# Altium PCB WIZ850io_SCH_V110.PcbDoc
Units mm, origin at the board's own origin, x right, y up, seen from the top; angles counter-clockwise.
Board outline 23 x 25 mm, 4 copper layers (Top Layer, Internal Plane 1, Internal Plane 2, Bottom Layer); 39 components, 31 nets, 148 pads, 214 vias.
Unrouted connection lines stored in the file: 1.
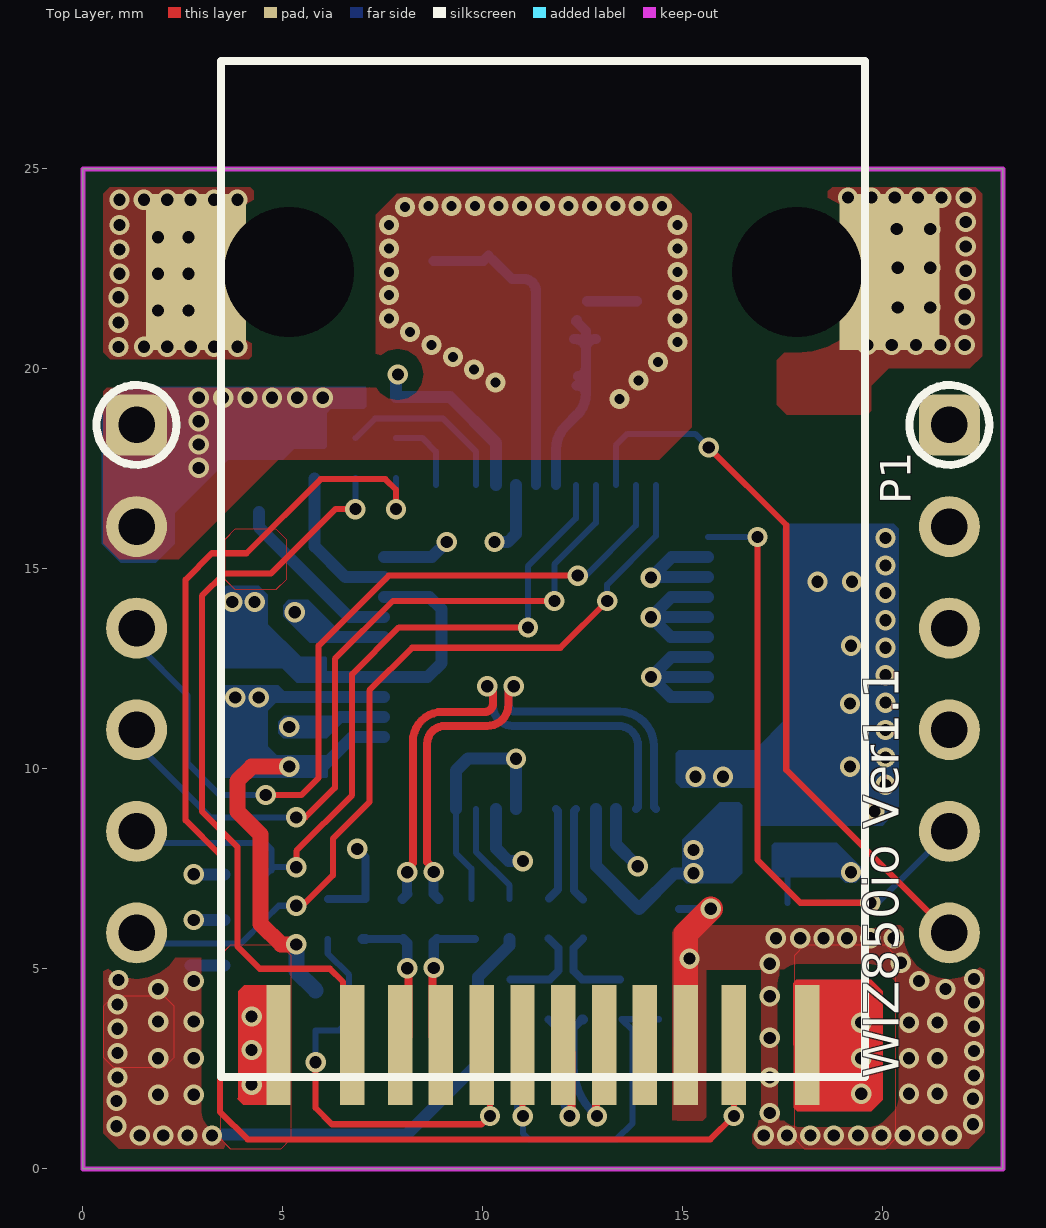
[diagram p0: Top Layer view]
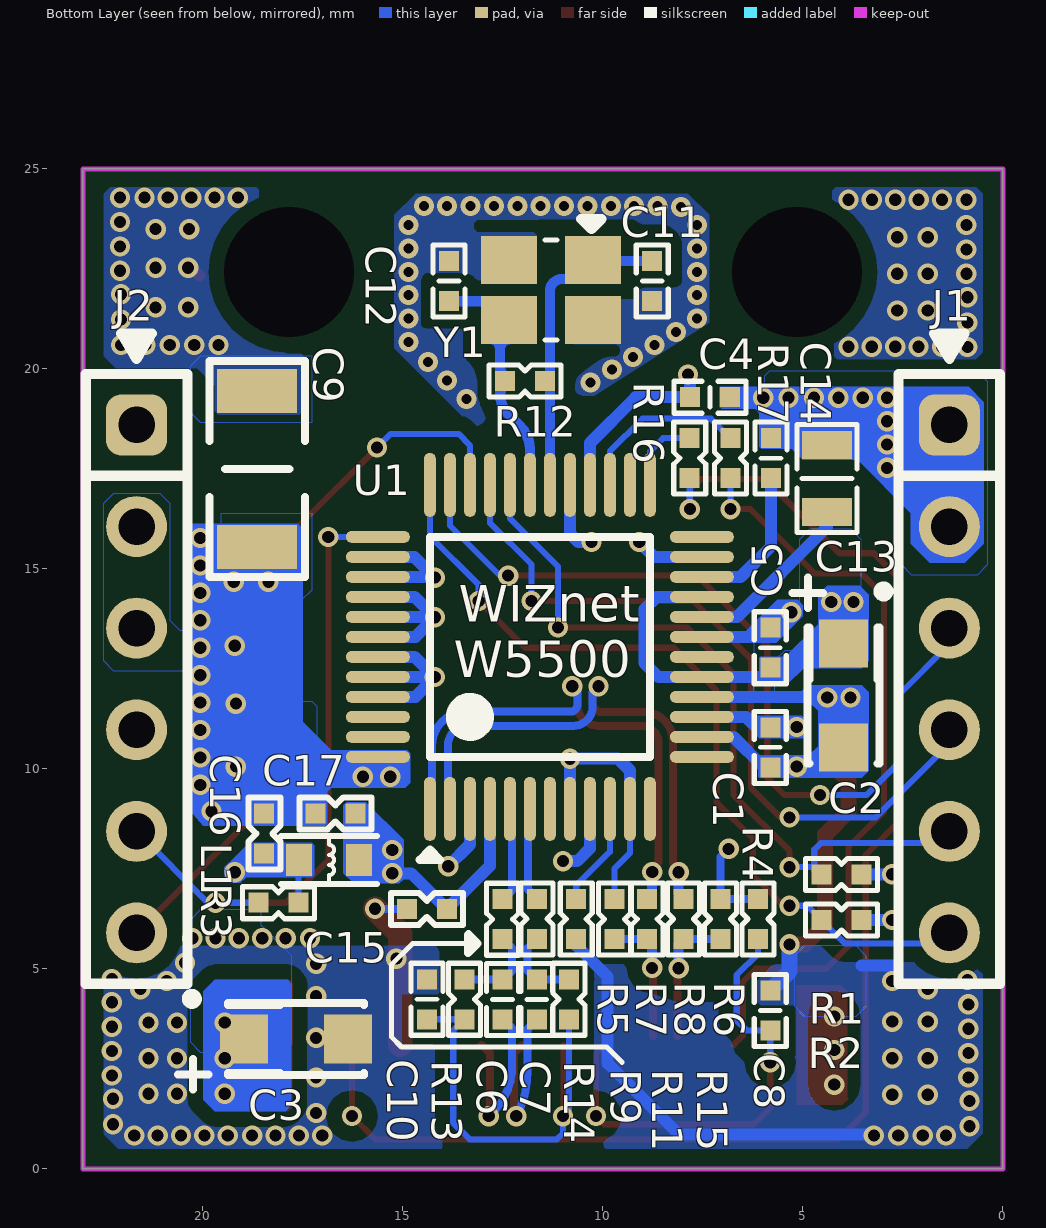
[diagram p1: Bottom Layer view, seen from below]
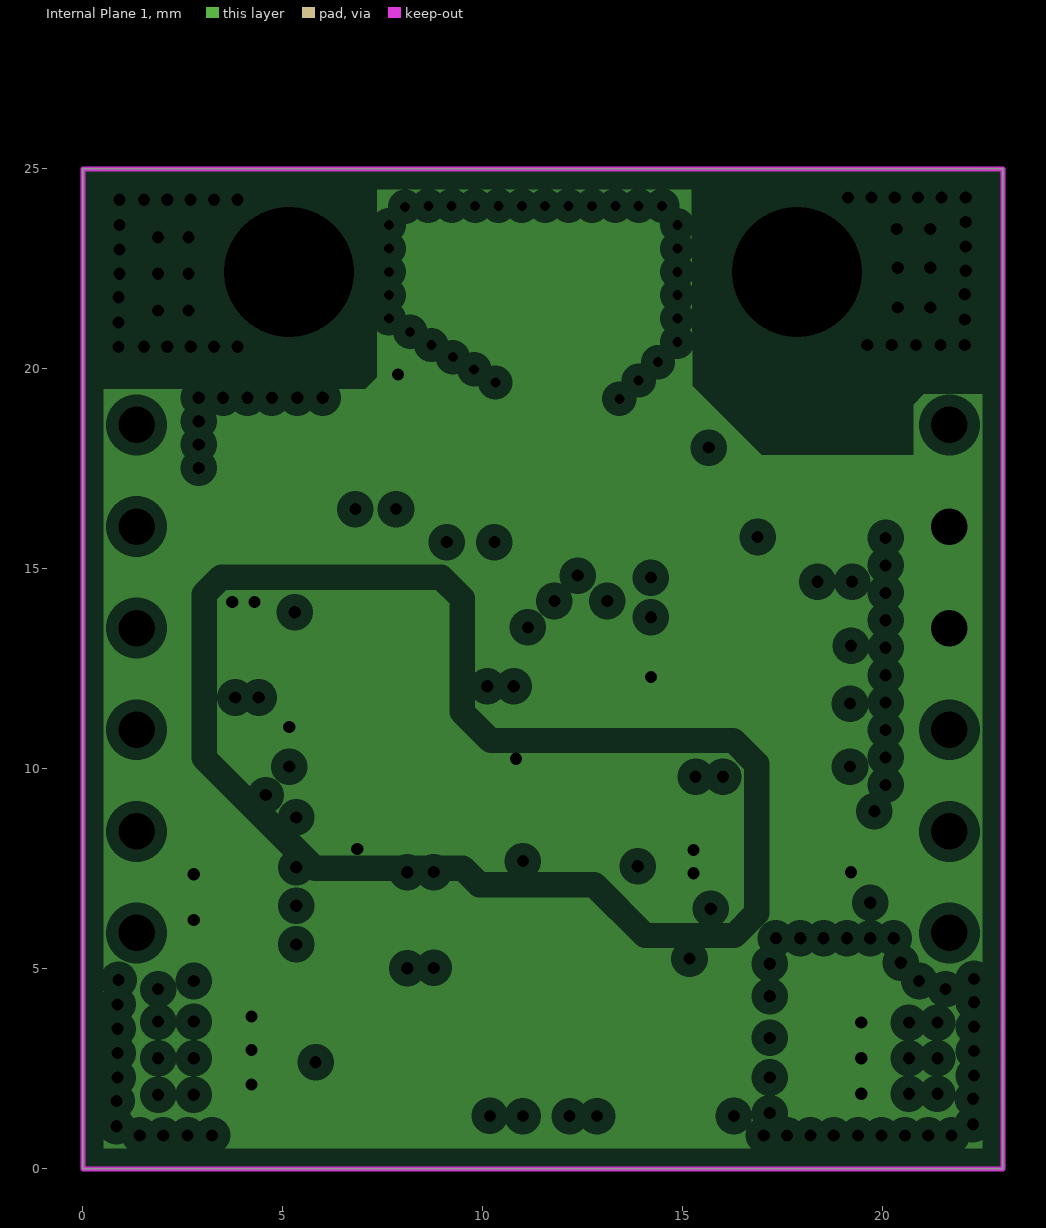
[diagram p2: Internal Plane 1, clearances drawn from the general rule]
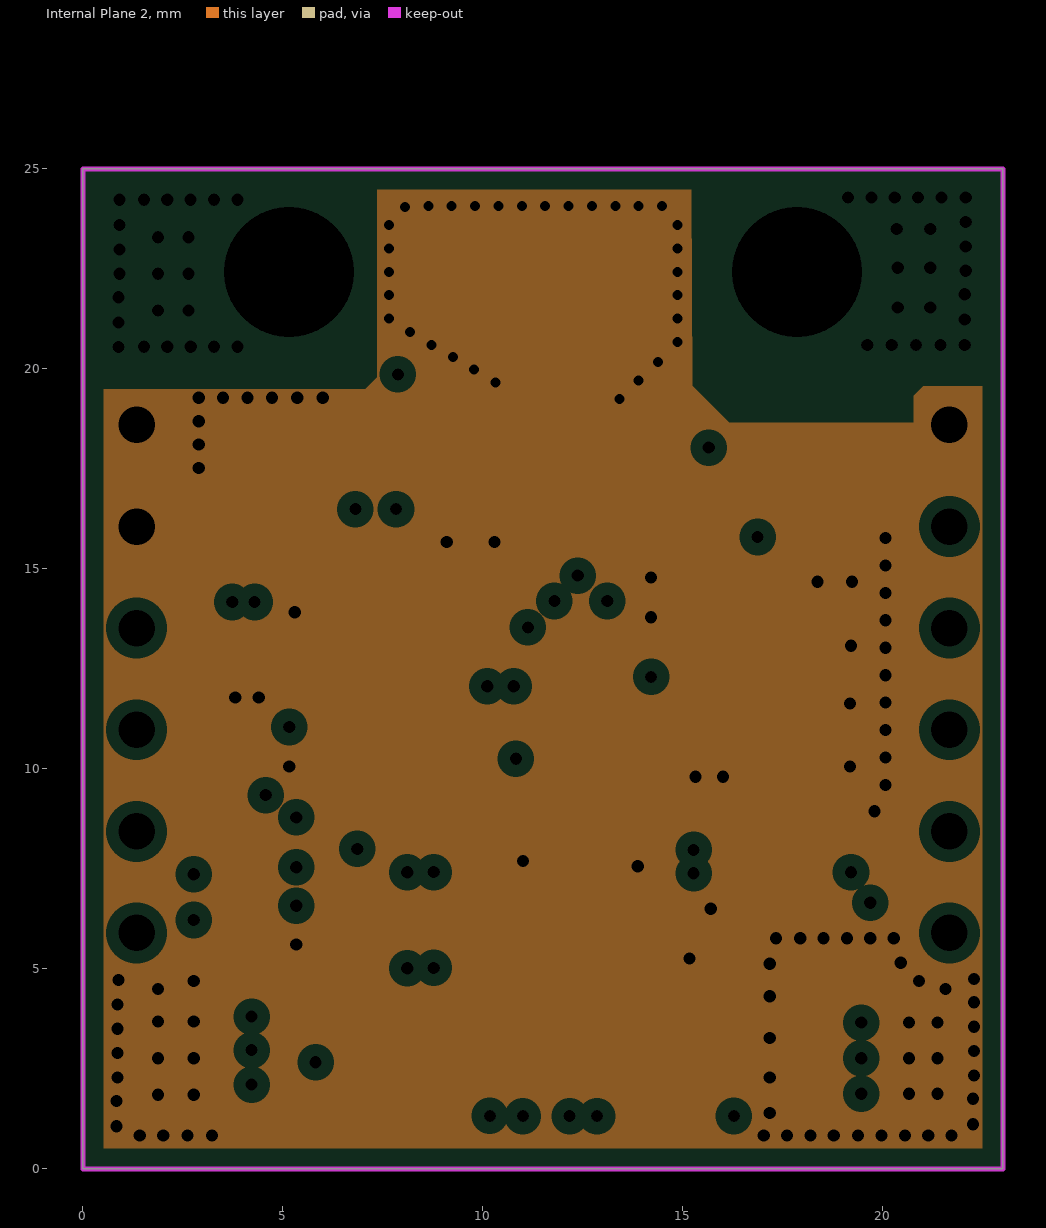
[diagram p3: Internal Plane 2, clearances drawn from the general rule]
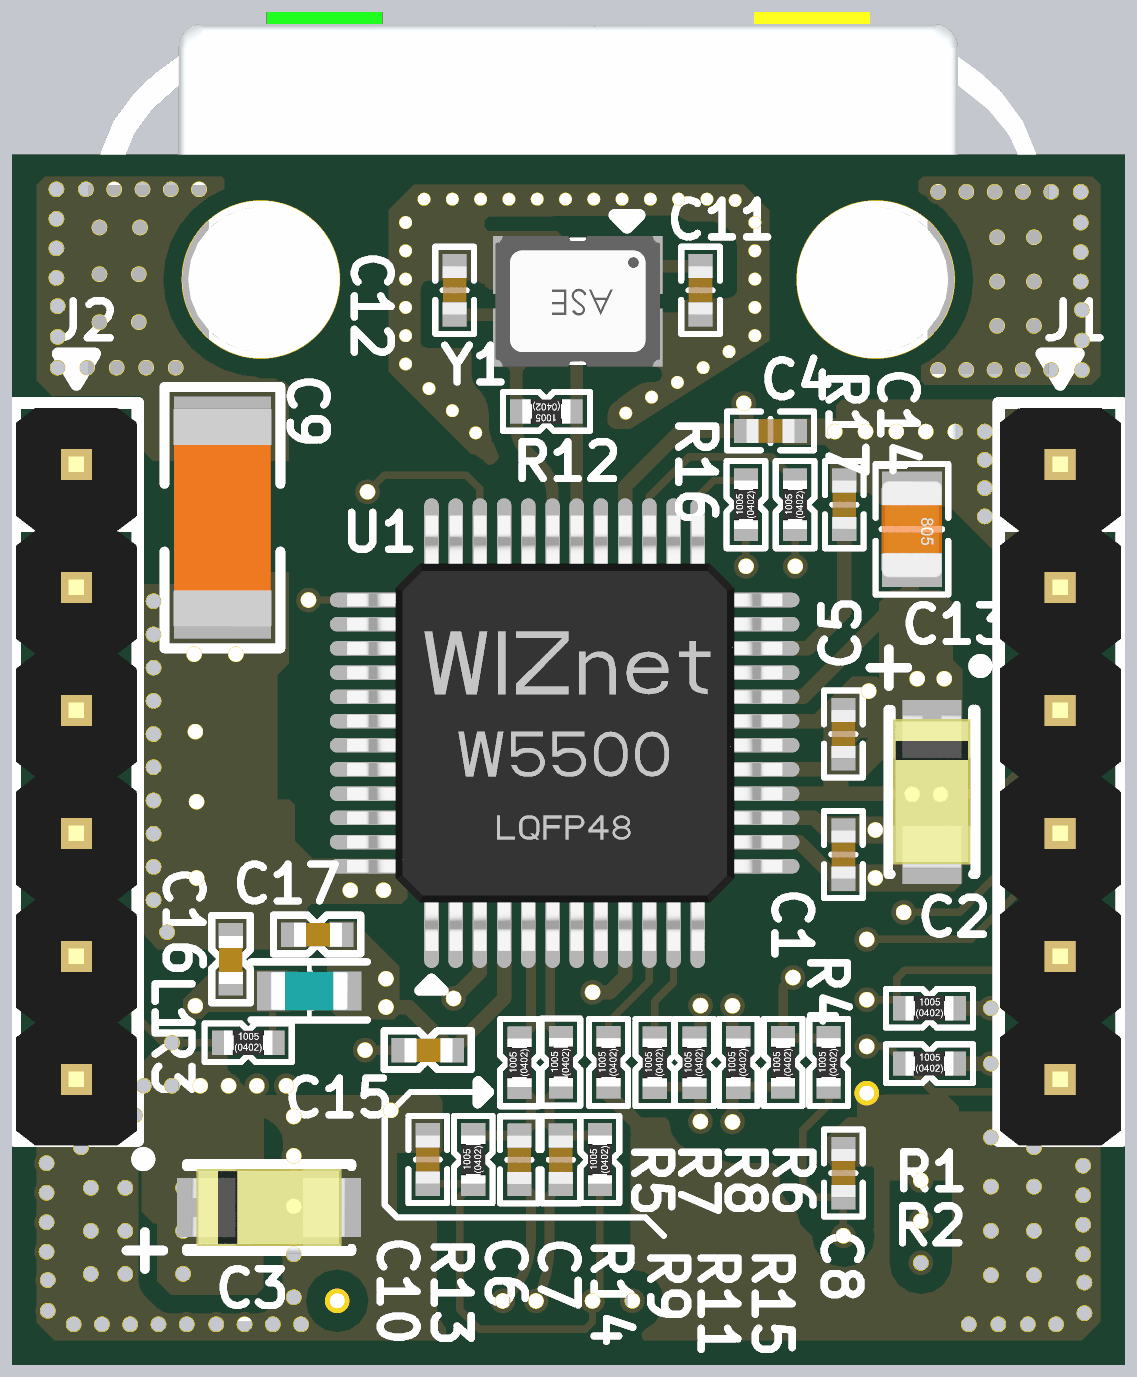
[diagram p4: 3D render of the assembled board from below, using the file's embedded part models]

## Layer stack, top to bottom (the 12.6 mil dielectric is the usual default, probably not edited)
Top Solder: solder mask 0.0102, Solder Resist, Dk 3.5
Top Layer: signal copper 0.0356
Dielectric1: dielectric 0.32, FR-4, Dk 4.8
Internal Plane 1: plane copper 0.0356, net 3.3V_D
Dielectric2: dielectric 0.32, FR-4, Dk 4.8
Internal Plane 2: plane copper 0.0356, net GND
Dielectric3: dielectric 0.32, FR-4, Dk 4.8
Bottom Layer: signal copper 0.0356
Bottom Solder: solder mask 0.0102, Solder Resist, Dk 3.5

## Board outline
0,0 23,0 23,25 0,25

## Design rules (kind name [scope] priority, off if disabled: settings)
Clearance [All] p1: gap=0.152 ignorepadtopadclearanceinfootprint=FALSE except(0: Arc-Hole Track-Hole SMDPad-Hole THPad-Hole Via-Hole Fill-Hole Poly-Hole Region-Hole Text-Hole; 0.381: Arc-Poly Track-Poly SMDPad-Poly THPad-Poly Via-Poly Fill-Poly Poly-Poly Poly-Region)
DiffPairsRouting [All] p1: maxlimit=0.152 minlimit=0.152 mostfreqgap=0.152 toplayer_minwidth=0.152 toplayer_maxwidth=0.152 toplayer_prefwidth=0.152 bottomlayer_minwidth=0.152 bottomlayer_maxwidth=0.152 bottomlayer_prefwidth=0.152 maxuncoupledlength=12.7
HoleSize [All] p1: absolutevalues=TRUE maxlimit=25.4 minlimit=0.025 maxpercent=80.000 minpercent=20.000
PlaneClearance [All] p1: clearance=0.305
PlaneConnect [All] p1: planeconnectstyle=Direct reliefexpansion=0.508 reliefentries=4 reliefconductorwidth=0.254 reliefairgap=0.254
PolygonConnect [All] p1: connectstyle=Direct reliefconductorwidth=0.254 reliefentries=4 polygonreliefangle="90 Angle" airgapwidth=0.254
RoutingVias [All] p1: holewidth=0.305 width=0.508 viastyle="Through Hole" minholewidth=0.305 minwidth=0.508 maxholewidth=0.711 maxwidth=1.27
SolderMaskExpansion [All] p1: expansion=0 istentingtop=FALSE
Width [All] p1: maxlimit=1 minlimit=0.15 preferedwidth=0.15 minimp=50.000000 maximp=50.000000 favimp=50.000000
26 further rules are at their usual default settings.

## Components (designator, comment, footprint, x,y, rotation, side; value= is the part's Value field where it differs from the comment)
C1 "0.1uF" CAP-0402#1 5.817,10.541 r90 bottom
C2 "10uF/16V" "CAP-A SIZE" 3.988,11.836 r270 bottom
C3 "10uF/16V" "CAP-A SIZE" 17.678,3.251 r180 bottom
C4 "0.1uF" CAP-0402#1 7.322,19.293 r0 bottom
C5 "1uF" CAP-0402#1 5.817,13.03 r270 bottom
C6 "6.8nF" CAP-0402#1 12.51,4.237 r90 bottom
C7 "6.8nF" CAP-0402#1 11.654,4.239 r90 bottom
C8 "22nF" CAP-0402#1 5.817,3.962 r270 bottom
C9 "1nF/2kV" CAP-1808 18.644,17.501 r90 bottom
C10 "10nF" CAP-0402#1 14.402,4.242 r270 bottom
C11 "18pF" CAP-0402#1 8.767,22.197 r90 bottom
C12 "18pF" CAP-0402#1 13.847,22.197 r270 bottom
C13 "4.7uF" CAP-0805 4.401,17.261 r270 bottom
C14 "10nF" CAP-0402#1 5.798,17.769 r270 bottom
C15 "0.1uF" CAP-0402#2 14.402,6.502 r180 bottom
C16 "0.1uF" CAP-0402#2 18.466,8.382 r270 bottom
C17 "0.1uF" CAP-0402#2 16.688,8.89 r180 bottom
J1 "2.54mm 1x6 Pin Header DIP" IDC-1X6 1.34,18.6 r270 bottom locked
J2 "2.54mm 1x6 Pin Header DIP" IDC-1X6 21.66,18.6 r270 bottom locked
L1 "HH-1M1608-121JT" IND-0603 16.85,7.725 r180 bottom
P1 "BS-R250210" BS-R250210 11.5,15 r180 top locked
R1 "4.7K" RES-0402 4.039,7.366 r180 bottom
R2 "4.7K" RES-0402 4.039,6.223 r180 bottom
R3 "4.7K" RES-0402 18.11,6.655 r180 bottom
R4 "10R" RES-0402 6.121,6.248 r90 bottom
R5 "49R9" RES-0402 9.713,6.245 r90 bottom
R6 "49R9" RES-0402 7.061,6.248 r90 bottom
R7 "33R" RES-0402 8.893,6.245 r90 bottom
R8 "33R" RES-0402 7.988,6.247 r90 bottom
R9 "33R" RES-0402 12.507,6.243 r90 bottom
R11 "33R" RES-0402 11.651,6.252 r90 bottom
R12 "1M" RES-0402 11.951,19.695 r0 bottom
R13 "49R9" RES-0402 13.462,4.242 r90 bottom
R14 "49R9" RES-0402 10.846,4.242 r90 bottom
R15 "12.4K" RES-0402 10.668,6.248 r90 bottom
R16 "330R" RES-0402 7.83,17.769 r90 bottom
R17 "330R" RES-0402 6.814,17.769 r90 bottom
U1 "W5500" "WIZNET W5500" 11.575,13.05 r180 bottom locked
Y1 "25MHz" OSC-82J0626 11.303,21.971 r0 bottom

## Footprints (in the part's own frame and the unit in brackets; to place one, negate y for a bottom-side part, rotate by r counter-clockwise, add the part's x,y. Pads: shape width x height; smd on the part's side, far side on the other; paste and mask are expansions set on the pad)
BS-R250210 [mm] "BS-R250210"
  rect 0.61x3 smd: L1(6.61,11.9) L2(4.77,11.9) L3(-4.77,11.9) L4(-6.61,11.9) R1(3.57,11.9) R2(2.55,11.9) R3(1.53,11.9) R4(0.51,11.9) R5(-0.51,11.9) R6(-1.53,11.9) R7(-2.55,11.9) R8(-3.57,11.9)
  rect 2.5x3.9 smd: S1(-8.67,-7.42) S2(8.67,-7.42)
  round 0 hole 3.25: ""(-6.35,-7.42) ""(6.35,-7.42)
  silkscreen extent -8.05,-12.7 8.05,12.7, body extent -9.75,-12.95 9.75,14.1, height 14.58
CAP-0402#1 [mm] "Ceramic CAP 0402(1005)"
  rect 0.5x0.5 smd: 1(-0.5,0) 2(0.5,0)
  silkscreen extent -0.9,-0.4 0.9,0.4, body extent -0.5,-0.25 0.5,0.25, height 0.6
CAP-0402#2 [mm] "Ceramic CAP 0402(1005)"
  rect 0.5x0.5 smd: 1(-0.5,-0.004) 2(0.5,-0.004)
  silkscreen extent -0.9,-0.4 0.9,0.4, body extent -0.48,-0.25 0.52,0.25, height 0.6
CAP-0805 [mm] "Ceramic CAP 0805(2012)"
  rect 0.7x1.245 smd: 1(-0.839,0) 2(0.839,0)
  silkscreen extent -1.35,-0.75 1.35,0.75, body extent -1,-0.62 1,0.62, height 0.78
CAP-1808 [mm] "Ceramic CAP 1808(4520)"
  rect 1.1x2 smd: 1(-1.95,0) 2(1.95,0)
  silkscreen extent -2.7,-1.2 2.7,1.2, body extent -2.25,-1.02 2.25,1.01, height 2
"CAP-A SIZE" [mm] "Tantal CAP A Size EIA/IECQ 3216"
  rect 1.2x1.22 smd: 1(-1.3,0) 2(1.3,0)
  silkscreen extent -2.95,-1.27 1.7,1.12, body extent -1.6,-0.8 1.59,0.8
IDC-1X6 [mil]
  rrect50% 60x60 hole 36: 1(0,0)
  round 60 hole 36: 2(100,0) 3(200,0) 4(300,0) 5(400,0) 6(500,0)
  silkscreen extent -90,-50 550,50, body extent -46,-49 554,49, height 323
IND-0603 [mm] "Inductor 0603(1608)"
  rect 0.65x0.8 smd: 1(-0.75,0) 2(0.75,0)
  silkscreen extent -1.2,-0.6 1.2,0.6, body extent -0.8,-0.4 0.8,0.4, height 0.95
OSC-82J0626 [mm]
  rect 1.4x1.2 smd: 1(-1.05,-0.75) 2(1.05,-0.75) 3(1.05,0.75) 4(-1.05,0.75)
  silkscreen extent -1.27,-1.78 0.15,1.25, body extent -1.7,-1.35 1.7,1.35, height 1.06
RES-0402 [mm]
  rect 0.5x0.5 smd: 1(-0.5,0) 2(0.5,0)
  silkscreen extent -0.9,-0.4 0.9,0.4, body extent -0.5,-0.25 0.5,0.25, height 0.35
"WIZNET W5500" [mm]
  oval 0.3x1.6 smd: 1(-2.75,-4.05) 2(-2.25,-4.05) 3(-1.75,-4.05) 4(-1.25,-4.05) 5(-0.75,-4.05) 6(-0.25,-4.05) 7(0.25,-4.05) 8(0.75,-4.05) 9(1.25,-4.05) 10(1.75,-4.05) 11(2.25,-4.05) 12(2.75,-4.05) 25(2.75,4.05) 26(2.25,4.05) 27(1.75,4.05) 28(1.25,4.05) 29(0.75,4.05) 30(0.25,4.05) 31(-0.25,4.05) 32(-0.75,4.05) 33(-1.25,4.05) 34(-1.75,4.05) 35(-2.25,4.05) 36(-2.75,4.05)
  oval 1.6x0.3 smd: 13(4.05,-2.75) 14(4.05,-2.25) 15(4.05,-1.75) 16(4.05,-1.25) 17(4.05,-0.75) 18(4.05,-0.25) 19(4.05,0.25) 20(4.05,0.75) 21(4.05,1.25) 22(4.05,1.75) 23(4.05,2.25) 24(4.05,2.75) 37(-4.05,2.75) 38(-4.05,2.25) 39(-4.05,1.75) 40(-4.05,1.25) 41(-4.05,0.75) 42(-4.05,0.25) 43(-4.05,-0.25) 44(-4.05,-0.75) 45(-4.05,-1.25) 46(-4.05,-1.75) 47(-4.05,-2.25) 48(-4.05,-2.75)
  silkscreen extent -3,-5.32 2.75,2.75, body extent -4.5,-4.5 4.5,4.5, height 1.65

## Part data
C1 C4 C5 C6 C7 C8 C10 C11 C12 C13 C15 C16 C17: library part CAP-0402, "Ceramic CAP 0402(1005)"
C2 C3: library part "CAP-A Size", "Tantla CAP A Size EIA/IECQ 3216"
C9: library part CAP-1808, "Ceramic CAP 1808(4520)"
C14: library part CAP-0805, "Ceramic CAP 0805(2012)"
L1: library part IND-0603, "Inductor 0603(1608)"
R1 R2 R3 R4 R5 R6 R7 R8 R9 R11 R12 R13 R14 R15 R16 R17: library part RES-0402, "RES-0402"
U1: "WIZnet W5500"
Y1: library part OSC-82J0626-25MHz, "X-tal 25MHz,3.2x2.5 SMD, CL=18pF"

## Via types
v1: diameter 0.508, hole 0.305, Top Layer to Bottom Layer, tented both sides, 181 vias
v2: diameter 0.5, hole 0.25, Top Layer to Bottom Layer, tented both sides, 31 vias
v3: diameter 0.508, hole 0.305, Top Layer to Bottom Layer, 2 vias

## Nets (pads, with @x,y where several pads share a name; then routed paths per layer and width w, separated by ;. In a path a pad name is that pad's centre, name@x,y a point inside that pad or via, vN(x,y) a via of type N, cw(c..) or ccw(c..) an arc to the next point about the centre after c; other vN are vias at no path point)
3.3V_A: C1.2 C2.1 C5.2 C15.2 C17.2 L1.2 R4.2 R5.2 R6.2 U1.4 U1.8 U1.11 U1.15 U1.17 U1.21 | length 21.8
  Bottom Layer w0.152: U1.11 9.325,7.896 9.713,7.508 R5.2
  Bottom Layer w0.2: R4.2 R6.2 7.061,7.798 v1(6.858,8.001)
  Bottom Layer w0.3: v1(5.156,11.049) 5.164,11.041 C1.2@5.842,11.041 ; C5.2@5.817,12.403 5.92,12.3 U1.17 7.531,12.294 8.611,12.294 8.966,12.649 8.966,13.995 8.662,14.3 U1.21 ; C1.2@6.045,10.947 6.071,10.947 6.423,11.3 U1.15 ; U1.11 9.325,9.96 9.627,10.262 10.82,10.262 v1(10.825,10.257) U1.8 ; U1.4 12.825,7.575 C15.2 14.795,7.391 v1(15.265,7.391)
  other v1: 15.265,7.976 3.734,14.173 4.293,14.173
3.3V_D: C3.1 C4.2 C16.2 J2.2 J2.3 L1.1 P1.L1 P1.L4 R1.2 R2.2 R3.2 U1.28 U1.43 U1.44 U1.45 | length 11.9
  Bottom Layer w0.152: R3.2 L1.1@17.61,7.715
  Bottom Layer w0.3: v1(2.769,6.223) R2.2 ; v1(2.769,7.366) R1.2 ; v1(7.874,19.863) 7.822,19.811 C4.2 9.181,19.293 10.325,18.148 U1.28 ; U1.45 14.692,11.8 14.205,12.287 v1(14.205,12.3) ; U1.44 v1(14.205,12.3) ; U1.43 14.705,12.8 v1(14.205,12.3) ; L1.1 L1.1@17.603,7.722 ; L1.1@17.61,7.715 L1.1@17.603,7.722 ; L1.1@17.629,7.696 L1.1@17.603,7.722
  other v1: 19.456,1.88 4.216,2.108 19.456,2.769 4.216,2.972 19.456,3.658 4.216,3.81 19.202,7.417
ACT_LED: R17.2 U1.27 | length 4.4
  Bottom Layer w0.152: R17.2 7.302,18.757 9.005,18.757 9.825,17.937 U1.27
CH_GND: C9.2 P1.S1 P1.S2 | length 0.1
  Top Layer w0.3: P1.S1@20.091,22.341 P1.S1
  other v1: 0.889,20.549 1.525,20.552 2.109,20.552 2.693,20.552 3.278,20.552 3.862,20.552 19.609,20.599 20.218,20.599 20.828,20.599 21.438,20.599 22.047,20.599 0.889,21.158 22.047,21.234 1.88,21.463 2.642,21.463 20.371,21.539 21.184,21.539 0.889,21.793 22.047,21.869 0.914,22.377 1.88,22.377 2.642,22.377 22.073,22.454 20.371,22.53 21.184,22.53 0.914,22.987 22.073,23.063 1.88,23.292 2.642,23.292 20.345,23.495 21.184,23.495 0.914,23.597 22.073,23.673 0.914,24.232 1.524,24.232 2.108,24.232 2.692,24.232 3.277,24.232 3.861,24.232 19.126,24.282 19.71,24.282 20.295,24.282 20.879,24.282 21.463,24.282 22.073,24.282
GND: C1.1 C2.2 C3.2 C4.1 C5.1 C8.1 C9.1 C10.1 C11.1 C12.1 C13.1 C14.1 C15.1 C16.1 C17.1 J1.1 J1.2 J2.1 P1.R8 R15.1 U1.3 U1.9 U1.14 U1.16 U1.19 U1.23 U1.29 U1.38 U1.39 U1.40 U1.41 U1.42 U1.48 Y1.2 Y1.4 | length 47.2
  Top Layer w0.4: v1(5.156,10.058) 4.216,10.058 3.861,9.703 3.861,8.941 4.445,8.357 4.445,6.121 4.953,5.613 v3(5.334,5.613)
  Top Layer w0.61: P1.R8 15.07,5.875 v1(15.697,6.502)
  Bottom Layer w0.2: C15.1 14.906,6.502 v1(15.697,6.502)
  Bottom Layer w0.3: 2.692,5.08 3.539,5.08 ; v1(3.226,0.838) 3.251,0.864 8.103,0.864 9.881,2.642 9.881,4.801 10.668,5.588 R15.1 ; v1(4.394,11.786) 4.347,11.786 4.332,11.8 U1.16 ; v1(5.156,10.058) 5.994,10.058 6.735,10.8 U1.14 ; C5.1@5.817,13.403 5.92,13.3 U1.19 ; U1.23 8.721,15.3 v1(9.093,15.672) ; v1(10.287,15.672) 10.617,15.672 10.825,15.88 U1.29 ; U1.9 10.325,8.014 10.643,7.696 v1(10.998,7.696) ; U1.3 13.325,8.113 v1(13.868,7.569) ; v1(14.199,14.783) v1@14.216,14.8 ; U1.42 14.691,13.3 v1(14.199,13.792) v1@14.206,13.8 ; U1.41 v1@14.206,13.8 ; U1.40 14.706,14.3 v1@14.206,13.8 ; U1.39 v1@14.216,14.8 ; U1.38 14.716,15.3 v1@14.216,14.8 ; v1@19.346,10.1 19.844,9.601 v1(20.066,9.601)
  Bottom Layer w0.4: v3(5.334,5.613) 5.334,4.945 C8.1
  other v1: 1.422,0.838 2.007,0.838 2.616,0.838 17.018,0.838 17.602,0.838 18.186,0.838 18.771,0.838 19.38,0.838 19.964,0.838 20.549,0.838 21.133,0.838 21.717,0.838 0.838,1.067 22.25,1.118 17.17,1.397 0.838,1.702 22.25,1.753 1.88,1.854 2.769,1.854 20.65,1.88 21.361,1.88 0.864,2.286 17.17,2.286 22.276,2.337 1.88,2.769 2.769,2.769 20.65,2.769 21.361,2.769 0.864,2.896 22.276,2.946 17.17,3.277 0.864,3.505 22.276,3.556 20.65,3.658 21.361,3.658 1.88,3.683 2.769,3.683 0.864,4.115 22.276,4.166 17.17,4.318 1.88,4.496 21.565,4.496 2.769,4.699 20.904,4.699 0.889,4.724 22.276,4.75 17.17,5.131 20.447,5.156 15.164,5.258 17.323,5.766 17.932,5.766 18.517,5.766 19.101,5.766 19.685,5.766 20.269,5.766 19.787,8.941 15.316,9.804 16.002,9.804 19.177,10.058 20.066,10.287 20.066,10.973 19.177,11.633 20.066,11.659 3.81,11.786 20.066,12.344 20.066,13.03 19.202,13.081 20.066,13.716 5.294,13.918 20.066,14.402 18.364,14.681 19.228,14.681 20.066,15.088 20.066,15.773 2.896,17.526 2.896,18.11 2.896,18.694 2.896,19.279 3.505,19.279 4.115,19.279 4.724,19.279 5.359,19.279 5.994,19.279
  other v2: 13.411,19.253 10.312,19.66 13.894,19.71 9.779,19.99 14.376,20.168 9.246,20.295 8.712,20.599 14.859,20.676 8.179,20.93 7.645,21.26 14.859,21.26 7.645,21.844 14.859,21.844 7.645,22.428 14.859,22.428 7.645,23.012 14.859,23.012 7.645,23.597 14.859,23.597 8.052,24.054 8.636,24.079 9.22,24.079 9.804,24.079 10.389,24.079 10.973,24.079 11.557,24.079 12.141,24.079 12.725,24.079 13.31,24.079 13.894,24.079 14.478,24.079
INTN: J1.6 R2.1 U1.36 | length 21
  Top Layer w0.152: v1(5.334,6.579) 5.486,6.579 6.248,7.341 6.248,8.255 7.163,9.169 7.163,11.963 8.23,13.03 11.938,13.03 v1(13.106,14.199)
  Bottom Layer w0.152: J1.6 1.601,5.639 3.954,5.639 R2.1 4.894,6.579 v1(5.334,6.579) ; v1(13.106,14.199) 13.106,14.605 14.325,15.824 U1.36
LINK_LED: R16.2 U1.25 | length 2
  Bottom Layer w0.152: R16.2 8.492,18.269 8.825,17.935 U1.25
MISO: J2.6 U1.34 | length 18.2
  Top Layer w0.152: v1(15.646,18.034) 17.582,16.098 17.582,9.978 J2.6
  Bottom Layer w0.152: U1.34 13.325,18.09 13.61,18.375 15.305,18.375 v1(15.646,18.034)
MOSI: J1.3 U1.35 | length 21.2
  Top Layer w0.152: v1(4.572,9.347) 5.461,9.347 5.893,9.779 5.893,13.081 7.645,14.834 v1(12.37,14.834)
  Bottom Layer w0.152: J1.3 1.34,13.113 2.616,11.836 2.616,10.146 3.415,9.347 v1(4.572,9.347) ; v1(12.37,14.834) 12.573,14.834 13.825,16.086 U1.35
NetC6_1: C6.1 P1.R6 | length 4.6
  Top Layer w0.2: v1(12.852,1.321) 12.824,1.349 12.824,2.894 P1.R6
  Bottom Layer w0.2: C6.1@12.48,3.739 12.268,3.527 12.268,2.591 ccw(c13.906,2.575) v1(12.852,1.321)
  Bottom Layer w0.256: C6.1@12.48,3.739 C6.1@12.501,3.739
NetC6_2: C6.2 R9.1 R13.2 | length 2.1
  Bottom Layer w0.2: C6.2@12.473,4.741 12.268,4.946 12.268,5.523 R9.1@12.506,5.761 ; C6.2@12.501,4.739 13.421,4.739 R13.2@13.423,4.741
NetC7_1: C7.1 P1.R5 | length 4.4
  Top Layer w0.2: P1.R5 12.217,2.893 v1@12.217,1.372
  Bottom Layer w0.2: C7.1@11.644,3.739 11.887,3.496 11.887,2.429 ccw(c14.159,2.413) v1(12.167,1.321)
NetC7_2: C7.2 R11.1 R14.2 | length 2.2
  Bottom Layer w0.2: R14.2@10.693,4.742 10.696,4.739 C7.2@11.644,4.739 ; R11.1@11.645,5.761 11.887,5.519 11.887,4.955 C7.2@11.673,4.741
NetC8_2: C8.2 P1.R3 R4.1 | length 11.6
  Top Layer w0.152: v1(5.817,2.667) 5.817,1.524 6.223,1.118 9.968,1.118 v1(10.175,1.325) 10.175,2.895 P1.R3
  Bottom Layer w0.152: v1(5.817,2.667) C8.2 6.409,3.462 6.655,3.708 6.655,4.851 6.121,5.385 R4.1 R4.1@6.111,5.738
NetC10_2: C10.2 P1.R4 R13.1 R14.1 | length 11.5
  Top Layer w0.152: v1@10.99,1.177 10.998,1.185 v1(10.998,1.321) 10.99,1.329 P1.R4
  Bottom Layer w0.152: R14.1@10.839,3.746 R14.1@10.843,3.742 ; R14.1@10.852,3.742 10.852,1.467 v1(10.998,1.321) 10.998,0.889 11.151,0.737 13.335,0.737 13.741,1.143 13.741,3.462 R13.1 C10.2
NetC13_2: C13.2 U1.20 | length 4.4
  Bottom Layer w0.3: C13.2 4.401,16.046 6.647,13.8 U1.20
NetC14_2: C14.2 U1.22 | length 3.8
  Bottom Layer w0.152: C14.2@5.795,17.265 C14.2
  Bottom Layer w0.3: C14.2@5.795,17.265 5.795,15.567 6.561,14.8 U1.22
NetP1_L2: P1.L2 R17.1 | length 19.3
  Top Layer w0.152: P1.L2 6.502,3.328 6.502,4.674 6.172,5.004 4.42,5.004 3.861,5.563 3.861,8.052 2.972,8.941 2.972,14.326 3.531,14.884 4.699,14.884 6.311,16.496 v1(6.811,16.496)
  Bottom Layer w0.152: v1(6.811,16.496) 6.814,16.499 R17.1
NetP1_L3: P1.L3 R16.1 | length 36.5
  Top Layer w0.152: v1(7.827,16.496) 7.827,16.979 7.559,17.247 5.944,17.247 4.089,15.392 3.226,15.392 2.565,14.732 2.565,8.712 3.429,7.849 3.429,1.422 4.115,0.737 15.687,0.737 v3(16.273,1.323) 16.273,3.097 P1.L3
  Bottom Layer w0.152: v1(7.827,16.496) 7.83,16.499 R16.1
NetP1_R1: P1.R1 R6.1 R8.1 | length 3.5
  Top Layer w0.2: v1(8.108,5.017) 8.135,4.99 P1.R1@8.135,3.305
  Bottom Layer w0.2: R6.1@7.061,5.745 7.063,5.747 R8.1
  Bottom Layer w0.254: R6.1@6.996,5.745 R6.1@7.061,5.745 ; R8.1@8.01,5.742 8.108,5.644 v1(8.108,5.017)
NetP1_R2: P1.R2 R5.1 R7.1 | length 3.4
  Top Layer w0.2: P1.R2@8.745,3.305 8.745,5.002 v1(8.77,5.027)
  Bottom Layer w0.2: R7.1@8.852,5.748 R5.1@9.804,5.748
  Bottom Layer w0.254: v1(8.77,5.027) 8.77,5.666 R7.1@8.852,5.748
NetR7_2: R7.2 U1.1 | length 13.4
  Top Layer w0.2: v1@8.768,7.508 8.606,7.67 8.606,10.636 cw(c9.044,10.636) 9.044,11.074 10.107,11.074 ccw(c10.107,11.606) 10.638,11.606 10.638,11.934 v1(10.77,12.065)
  Top Layer w0.25: v1(8.768,7.422) v1@8.768,7.508
  Bottom Layer w0.2: v1(10.77,12.065) 10.639,11.934 10.639,11.609 ccw(c10.816,11.609) 10.816,11.431 13.417,11.431 cw(c13.417,10.576) 14.272,10.576 14.272,9.053 U1.1
  Bottom Layer w0.25: v1(8.768,7.422) 8.768,6.87 R7.2
NetR8_2: R8.2 U1.2 | length 13.4
  Top Layer w0.2: v1@8.107,7.512 8.248,7.653 8.248,10.686 cw(c8.988,10.686) 8.988,11.427 10.044,11.427 ccw(c10.044,11.638) 10.255,11.638 10.255,11.919 v1(10.109,12.065)
  Top Layer w0.25: v1(8.107,7.418) v1@8.107,7.512
  Bottom Layer w0.2: v1(10.109,12.065) 10.257,11.917 10.257,11.564 ccw(c10.742,11.564) 10.742,11.079 13.377,11.079 cw(c13.377,10.578) 13.878,10.578 13.878,9.053 U1.2
  Bottom Layer w0.25: R8.2 8.115,6.874 8.107,6.882 v1(8.107,7.418)
NetR9_2: R9.2 U1.5 | length 2.4
  Bottom Layer w0.2: U1.5 12.271,8.946 12.271,6.964 R9.2@12.5,6.735
NetR11_2: R11.2 U1.6 | length 2.3
  Bottom Layer w0.2: R11.2@11.651,6.764 11.875,6.988 11.875,8.95 U1.6
NetR15_2: R15.2 U1.10 | length 2.6
  Bottom Layer w0.152: U1.10 9.825,7.93 10.668,7.087 R15.2
RSTN: J2.5 R3.1 U1.37 | length 16.4
  Top Layer w0.152: v1(16.866,15.799) 16.866,7.722 17.932,6.655 v1(19.685,6.655)
  Bottom Layer w0.152: U1.37 v1(16.866,15.799) v1(16.866,15.799) ; R3.1 v1(19.685,6.655) 19.875,6.655 J2.5
SCLK: J1.4 U1.33 | length 19
  Top Layer w0.152: v1(5.334,8.788) 5.563,8.788 6.299,9.525 6.299,12.751 7.747,14.199 v1(11.786,14.199)
  Bottom Layer w0.152: J1.4 1.34,10.632 3.184,8.788 v1(5.334,8.788) ; v1(11.786,14.199) 11.786,15.113 12.825,16.152 U1.33
SCSN: J1.5 R1.1 U1.32 | length 19.3
  Top Layer w0.152: v1(5.334,7.544) 5.334,7.95 6.731,9.347 6.731,12.37 7.899,13.538 v1(11.125,13.538)
  Bottom Layer w0.152: J1.5 1.627,8.153 4.547,8.153 4.716,7.984 R1.1@4.716,7.468 ; R1.1 4.564,7.341 4.767,7.544 v1(5.334,7.544) ; v1(11.125,13.538) 11.125,15.062 12.325,16.262 U1.32
XI: C11.2 R12.1 U1.30 Y1.1 | length 7.7
  Bottom Layer w0.254: C11.2 10.007,22.697 Y1.1@10.142,22.832 ; Y1.1 10.726,22.248 11.021,22.248 cw(c11.021,21.944) 11.325,21.944 U1.30
XO: C12.2 R12.2 U1.31 Y1.3 | length 7.2
  Bottom Layer w0.254: U1.31 11.825,17.988 cw(c12.644,17.988) 12.065,18.567 12.361,18.863 ccw(c11.844,19.38) 12.575,19.38 12.575,20.945 12.326,21.194 Y1.3@12.351,21.219 ; Y1.3@12.273,20.747 cw(c12.309,20.482) 12.575,20.518 cw(c12.814,20.508) Y1.3@12.824,20.748 ; R12.2@12.344,19.583 cw(c12.357,19.367) 12.573,19.38 ; R12.2@12.377,19.819 ccw(c12.364,20.03) 12.575,20.044 ; Y1.3@12.606,21.693 C12.2@13.846,21.693
pads on no net: J2.4 P1. P1.R7 U1.7 U1.12 U1.13 U1.18 U1.24 U1.26 U1.46 U1.47

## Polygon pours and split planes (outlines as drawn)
GND on Top Layer "Top Layer-gnd" (solid, remove dead copper, pour order 66): 0.508,3.302 0.508,5.105 0.686,5.283 13.825,5.283 14.663,6.121 22.162,6.121 22.606,5.664 22.606,0.965 22.149,0.508 0.889,0.508 0.508,0.889
GND on Top Layer "Top Layer-NET" (solid, remove dead copper, shelved, pour order 54): 0.762,4.318 0.508,4.064 0.508,2.794 0.762,2.54 2.032,2.54 2.286,2.794 2.286,4.064 2.032,4.318
3.3V_A on Top Layer "Top Layer-net" (solid, remove dead copper, shelved, pour order 42): 5.08,15.621 5.08,14.732 4.826,14.478 3.81,14.478 3.556,14.732 3.556,15.748 3.81,16.002 4.826,16.002 5.08,15.748
3.3V_D on Top Layer "Keep-Out Layer-No Net" (solid, remove dead copper, shelved, pour order 26): 18.034,5.588 17.78,5.334 17.78,0.762 18.034,0.508 20.066,0.508 20.32,0.762 20.32,5.334 20.066,5.588
3.3V_D on Top Layer "Keep-Out Layer-No Net" (solid, remove dead copper, shelved, pour order 22): 3.683,5.588 3.429,5.334 3.429,0.762 3.683,0.508 4.953,0.508 5.207,0.762 5.207,5.334 4.953,5.588
GND on Top Layer "TOP Layer-gnd" (solid, pour order 76): 0.508,19.533 0.508,15.646 0.908,15.247 2.394,15.247 4.877,17.729 14.405,17.729 15.215,18.539 15.214,23.876 14.707,24.384 7.874,24.384 7.849,24.384 7.341,23.876 7.315,23.851 7.315,21.133 7.315,19.685 7.163,19.533
CH_GND on Top Layer "TOP Layer-CHGND" (solid, remove dead copper, pour order 78): 19.711,18.949 19.621,18.858 17.591,18.859 16.281,20.168 16.281,24.409 16.51,24.638 6.553,24.638 6.553,20.726 6.071,20.244 0.686,20.244 0.508,20.422 0.508,21.463 0.508,24.384 0.762,24.638 22.225,24.638 22.479,24.384 22.479,23.876 22.479,20.32 22.174,20.015 20.142,20.015 19.71,19.583
3.3V_A on Bottom Layer "Top Layer-net" (solid, remove dead copper, shelved, pour order 44): 3.556,15.621 3.556,13.081 3.683,12.954 5.461,12.954 5.715,12.7 5.715,11.684 6.223,11.684 6.223,13.589 5.715,13.589 5.334,13.589 5.08,13.843 5.08,13.97 5.08,15.748 4.826,16.002 3.81,16.002 3.556,15.748
no net on Bottom Layer "Top Layer-net" (solid, remove dead copper, shelved, pour order 40): 20.066,18.669 17.272,18.669 17.272,20.32 20.066,20.32 20.32,20.066 20.32,18.923
3.3V_D on Bottom Layer "Top Layer-net" (solid, remove dead copper, shelved, pour order 38): 18.796,12.446 22.225,12.446 22.479,12.7 22.479,16.637 22.225,16.891 21.082,16.891 20.828,16.637 20.828,16.256 20.828,13.716 20.574,13.462 20.32,13.462 19.05,13.462 18.796,13.208
no net on Bottom Layer "Top Layer-net" (solid, remove dead copper, shelved, pour order 36): 18.415,14.224 17.526,14.224 17.272,14.478 17.272,16.383 19.558,16.383 19.558,14.478 19.304,14.224
3.3V_A on Bottom Layer "Top Layer-NET" (solid, remove dead copper, shelved, pour order 34): 19.685,11.049 19.685,9.652 19.558,9.525 18.796,9.525 18.669,9.652 18.669,11.557 18.796,11.684 19.558,11.684 19.685,11.557
no net on Bottom Layer "Top Layer-NET" (solid, remove dead copper, shelved, pour order 32): 18.161,11.049 18.161,9.652 18.034,9.525 17.272,9.525 17.145,9.652 17.145,11.557 17.272,11.684 18.034,11.684 18.161,11.557
3.3V_D on Bottom Layer "Top Layer-NET" (solid, remove dead copper, shelved, pour order 24): 3.683,5.588 3.429,5.334 3.429,4.064 3.683,3.81 4.953,3.81 5.207,4.064 5.207,5.334 4.953,5.588
3.3V_D on Bottom Layer "Top Layer-net" (solid, remove dead copper, shelved, pour order 56): 20.32,5.334 20.32,3.175 20.066,2.921 18.034,2.921 17.78,3.175 17.78,5.334 18.542,6.096 18.542,6.477 19.304,6.477 20.066,6.477 20.32,6.223
GND on Bottom Layer "Top Layer-gnd" (solid, remove dead copper, shelved, pour order 58): 2.54,17.907 2.54,15.113 2.286,14.859 0.635,14.859 0.381,15.113 0.381,19.685 0.635,19.939 5.842,19.939 5.969,19.812 5.969,18.669 2.794,18.669 2.54,18.415
GND on Bottom Layer "Bottom Xtal-gnd" (solid, remove dead copper, pour order 60): 7.341,21.869 7.341,21.156 11.074,18.788 11.074,18.072 12.764,18.072 15.215,20.523 15.215,23.851 14.681,24.384 7.874,24.384 7.341,23.851
GND on Bottom Layer "Bottom Layer-below gnd" (solid, remove dead copper, pour order 62): 0.508,3.302 0.508,5.575 22.479,5.575 22.479,0.864 22.123,0.508 0.889,0.508 0.508,0.889
CH_GND on Bottom Layer "Bottom Layer-CHGND" (solid, remove dead copper, pour order 72): 19.711,18.949 19.621,18.858 17.591,18.859 16.281,20.168 16.281,24.409 16.51,24.638 6.553,24.638 6.553,20.726 6.071,20.244 0.686,20.244 0.508,20.422 0.508,21.463 0.508,24.384 0.762,24.638 22.225,24.638 22.479,24.384 22.479,23.876 22.479,20.32 22.174,20.015 20.142,20.015 19.71,19.583
GND on Internal Plane 2 (split plane): 15.24,19.583 16.154,18.669 20.752,18.669 20.752,19.329 21.006,19.584 22.49,19.584 22.49,0.51 0.51,0.51 0.51,19.507 7.061,19.507 7.341,19.787 7.341,24.49 15.215,24.49
3.3V_D on Internal Plane 1 (split plane): 15.24,19.583 16.973,17.85 20.752,17.85 20.752,19.102 21.025,19.375 22.49,19.375 22.49,0.51 0.51,0.51 0.51,19.507 7.061,19.507 7.341,19.787 7.341,24.49 15.215,24.49
3.3V_A on Internal Plane 1 (split plane): 9.161,14.136 9.161,11.423 9.167,11.361 9.186,11.301 9.215,11.246 9.255,11.197 9.966,10.486 10.014,10.446 10.07,10.417 10.129,10.399 10.192,10.393 16.13,10.393 16.527,9.995 16.527,6.526 16.155,6.154 14.185,6.154 13.008,7.33 12.96,7.37 12.904,7.4 12.845,7.418 12.782,7.424 10.044,7.424 9.725,7.743 9.676,7.783 9.621,7.813 9.561,7.831 9.499,7.837 5.923,7.837 3.35,10.41 3.35,14.236 3.588,14.474 8.824,14.474

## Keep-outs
Keep-Out Layer:
  the board outline again, w0.127
  text ".Layer_Name" at 9.398,29.718 h1.52

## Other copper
Top Layer:
  pour cut-out: 14.736,4.981 14.736,5.9 cw(c14.899,5.905) 14.78,6.017 14.961,6.198 14.961,6.248 14.529,6.248 14.529,4.978
  pour cut-out: 16.727,1.477 16.727,0.457 15.773,0.457
  region net 3.3V_D: 17.754,4.647 17.831,4.724 19.71,4.724 19.99,4.445 19.99,1.727 19.711,1.448 17.856,1.448 17.768,1.536
  region net 3.3V_D: 5.182,4.597 5.156,4.572 5.156,1.6 4.013,1.6 3.861,1.753 3.886,1.778 3.886,4.445 4.039,4.597
  pour cut-out: 18.821,6.096 21.057,6.096 21.057,6.325 21.057,6.362 18.821,6.362
  pour cut-out: 16.866,0.508 16.727,0.646 16.727,0.508
  pour cut-out: 16.24,24.663 16.24,23.774 18.622,23.774 18.621,24.504 18.78,24.663
  pour cut-out: 15.621,8.331 15.977,8.331 16.914,9.269 17.399,8.784 19.08,8.784 21.768,6.096 19.08,6.096 15.748,6.096 15.621,6.096
  pour cut-out: 16.281,21.193 16.849,20.625 17.85,20.404 17.534,20.404 17.348,20.218 17.348,18.593 16.662,18.593 16.281,18.974
  pour cut-out: 6.629,23.876 6.629,24.663 4.166,24.663 4.267,24.562 4.267,24.232 4.089,24.054 4.089,23.876
  pour cut-out: 6.706,20.93 6.706,20.196 4.092,20.196 4.216,20.32 4.216,20.65
  text ".Layer_Name" at 9.398,29.718 h1.52
Bottom Layer:
  pour cut-out: 10.998,18.694 11.074,18.694 11.074,21.969 10.947,21.969 9.576,21.969 9.25,22.295 9.023,22.295 8.407,22.295 8.353,22.349 8.353,23.058 8.383,23.088 9.271,23.088 9.423,23.24 9.423,23.317 9.576,23.47 11.1,23.47 11.176,23.47 11.227,23.419 11.227,23.186 11.477,22.936 11.477,22.835 11.477,21.969 11.71,21.969 13.094,21.969 13.325,22.2 14.376,22.2 14.377,21.158 13.438,21.16 13.286,21.008 13.286,20.422 12.817,20.422 12.817,19.152 12.267,18.603 12.267,18.061 12.759,18.06 13.336,18.637 cw(c13.173,18.836) 12.974,18.999 ccw(c12.574,19.399) 13.14,19.4 13.14,19.616 cw(c13.93,19.616) 13.372,20.175 ccw(c13.064,20.483) 13.5,20.484 13.5,20.868 cw(c13.697,20.868) 13.525,20.965 cw(c13.598,20.924) 13.599,21.008 14.388,21.008 ccw(c14.388,21.237) 14.5,21.037 ccw(c14.452,21.122) 14.55,21.122 14.55,22.159 ccw(c14.216,22.16) 14.506,22.326 ccw(c14.38,22.255) 14.38,22.4 13.497,22.4 ccw(c13.497,22.002) 13.215,22.283 13.052,22.12 11.653,22.12 11.653,23.337 11.735,23.419 13.094,23.419 ccw(c13.08,23.571) 13.08,23.724 11.871,23.724 11.605,23.734 9.316,23.741 ccw(c9.292,23.493) 9.227,23.734 ccw(c9.297,23.549) 9.172,23.702 cw(c8.886,24.077) 9.015,23.623 8.61,23.623 ccw(c8.609,23.002) 8.169,23.441 ccw(c8.536,23.073) 8.016,23.072 8.016,22.209 ccw(c8.167,22.208) 8.093,22.076 ccw(c8.267,22.387) 8.267,22.031 8.922,22.031 cw(c8.923,21.709) 9.151,21.936 9.217,21.869 ccw(c9.334,21.986) 9.334,21.821 10.953,21.821 10.953,20.661 10.913,20.621 9.727,20.621 ccw(c9.727,20.462) 9.727,20.303 9.804,20.303 cw(c9.806,19.786) 10.094,20.215 10.244,20.115 10.44,19.97 10.593,19.844 cw(c10.354,19.603) 10.693,19.602 10.693,19.513 cw(c10.51,19.512) 10.51,19.33 10.135,19.329
  pour cut-out: 14.093,5.373 cw(c14.312,5.395) 14.334,5.614 14.093,5.614 14.04,5.667 13.997,5.624 13.997,5.374
  pour cut-out: 14.199,3.048 14.275,3.124 14.199,3.124
  pour cut-out: 13.932,0.508 14.021,0.559 14.021,0.787 14.041,0.838 13.945,0.838
  pour cut-out: 3.569,3.81 3.569,2.108 4.864,2.108 4.864,3.81
  pour cut-out: 0.533,4.978 0.711,4.978 0.711,5.004 0.533,5.004
  pour cut-out: 5.664,5.131 5.794,5.077 5.893,4.978 5.893,5.131 5.867,5.156
  pour cut-out: 6.02,4.064 6.223,4.267 6.223,4.064
  pour cut-out: 6.464,2.667 6.706,2.908 6.807,3.226 6.706,3.124 6.452,3.124
  pour cut-out: 10.058,0.508 10.058,0.596 9.927,0.727 10.126,0.727 10.175,0.678
  pour cut-out: 10.215,3.111 10.215,2.012 10.175,1.972 10.215,1.85 10.386,1.679 10.386,3.111
  pour cut-out: 8.77,4.38 7.039,4.38 6.835,4.176 6.845,4.166 7.104,4.042 7.256,4.166 8.128,4.166
  pour cut-out: 14.079,4.428 14.155,4.352 14.079,4.352
  region net GND: 19.99,8.585 16.942,8.585 16.891,8.636 16.891,10.566 17.501,11.176 17.501,16.002 17.628,16.129 20.269,16.129 20.396,16.002 20.396,9.042
  region net 3.3V_D: 17.221,8.09 17.285,8.153 18.847,8.153 19.202,7.798 19.462,7.538 19.45,7.283 19.317,7.15 19.063,7.15 18.923,7.29 17.272,7.29 17.221,7.341
  region net 3.3V_D: 17.78,4.623 17.882,4.724 19.71,4.724 19.99,4.445 19.99,1.727 19.711,1.448 17.932,1.448 17.794,1.586
  region net 3.3V_A: 4.978,12.522 5.35,12.15 6.096,12.15 6.096,12.776 6.071,12.802 5.444,12.802 4.623,13.623 4.623,14.351 4.394,14.58 3.581,14.58 3.353,14.351 3.353,12.7 3.531,12.522
  region net GND: 3.352,11.912 3.353,9.957 3.531,9.779 6.096,9.779 6.121,9.804 6.121,10.287 6.07,10.338 4.851,10.338 4.623,10.566 4.623,11.455 4.826,11.659 5.055,11.659 5.055,11.913 4.877,12.09 3.531,12.09
  region net GND: 14.821,10.389 14.897,10.465 16.789,10.465 17.043,10.719 17.043,9.271 16.789,9.525 14.948,9.525 14.821,9.653
  region net 3.3V_A: 16.488,9.09 16.488,7.395 16.231,7.137 15.392,7.137 15.088,7.137 14.986,7.239 14.986,8.23 15.926,9.17 16.408,9.17
  region net GND: 3.632,17.729 5.004,17.729 5.283,18.009 6.045,18.009 6.096,18.059 6.096,18.898 6.198,18.999 7.036,18.999 7.086,19.05 7.086,19.533 7.069,19.55 4.386,19.55 0.856,19.55 0.475,19.169 0.475,15.625 0.95,15.15 1.825,15.15 2.3,15.625 2.3,16.397
  pour cut-out: 17.625,4.6 17.625,4.875 17.7,4.875 17.7,4.6
  pour cut-out: 19.95,4.8 19.95,4.675 19.9,4.675 19.9,4.8
  pour cut-out: 17.449,16.152 17.576,16.279 19.658,16.279 19.811,16.127 19.811,14.933 19.658,14.78 17.626,14.78 17.449,14.958
  pour cut-out: 16.24,24.663 16.24,23.876 18.704,23.876 18.603,23.977 18.603,24.486 18.78,24.663
  region net GND: 5.639,14.224 5.131,14.224 5.004,14.097 5.004,13.818 5.671,13.15 6.114,13.15 6.414,13.449
  region net 3.3V_A: 6.247,10.921 6.096,10.77 5.004,10.77 4.877,10.897 4.877,11.176 5.029,11.328 6.247,11.328
  pour cut-out: 16.294,21.167 16.862,20.599 17.863,20.379 17.547,20.379 17.361,20.193 17.361,18.567 16.675,18.567 16.294,18.948
  pour cut-out: 6.629,23.876 6.629,24.663 4.166,24.663 4.267,24.562 4.267,24.232 4.089,24.054 4.089,23.876
  pour cut-out: 6.706,20.93 6.706,20.196 4.092,20.196 4.216,20.32 4.216,20.65
  text ".Layer_Name" at 9.398,29.718 h1.52
Internal Plane 1 (plane layer: these items are gaps in the copper):
  pour cut-out: 7.061,19.507 7.341,19.787 7.341,24.536 0.483,24.536 0.483,19.535 0.51,19.507
  pour cut-out: 15.24,19.583 15.215,24.49 22.508,24.49 22.53,24.511 22.53,19.375 21.025,19.375 20.752,19.102 20.752,17.85 16.973,17.85
  lines w0.635: 3.031,10.277 5.791,7.518 9.499,7.518 9.912,7.105 12.782,7.105 14.052,5.835 16.288,5.835 16.846,6.394 16.846,10.127 16.262,10.712 10.192,10.712 9.48,11.423 9.48,14.269 8.956,14.793 3.456,14.793 3.031,14.368 3.031,10.277
  text ".Layer_Name" at 9.398,29.718 h1.52
Internal Plane 2 (plane layer: these items are gaps in the copper):
  pour cut-out: 7.061,19.507 7.341,19.787 7.341,24.536 0.483,24.536 0.483,19.535 0.51,19.507
  pour cut-out: 15.24,19.583 15.215,24.49 22.508,24.49 22.53,24.511 22.53,19.584 21.006,19.584 20.752,19.329 20.752,18.669 16.154,18.669
  text ".Layer_Name" at 9.398,29.718 h1.52

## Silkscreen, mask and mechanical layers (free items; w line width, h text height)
Top Overlay:
  text ".Layer_Name" at 9.398,29.718 h1.52
  text "Ver1.1" at 20.701,8.509 h1.52 r90
  text "WIZ850io" at 20.701,2.286 h1.52 r90
Bottom Overlay:
  lines w0.127: 9.525,2.667 9.906,3.048 15.037,3.048 15.291,3.302 15.291,5.105 14.757,5.639 13.792,5.639 ; 13.132,5.639 13.945,5.639
  lines w0.203: 13.36,5.867 13.132,5.639 13.373,5.397 13.373,5.855
  text ".Layer_Name" at 9.398,29.718 h1.52
Top Paste:
  text ".Layer_Name" at 9.398,29.718 h1.52
Bottom Paste:
  text ".Layer_Name" at 9.398,29.718 h1.52
Top Solder:
  text ".Layer_Name" at 9.398,29.718 h1.52
Bottom Solder:
  text ".Layer_Name" at 9.398,29.718 h1.52
Drill Guide:
  text ".Layer_Name" at 9.398,29.718 h1.52
Mechanical 2:
  the board outline again, w0.127
  text "BOARD NAME : WIZ850io" at 0,41.021 h1.52
  text "VERSION : V1.03" at 0,38.227 h1.52
  text "SIZE : 23mmX25mmX1.6T" at 0,35.433 h1.52
  text "GERBER DATE : 2017.12.05" at 0,32.385 h1.52
  text "LAYER :" at 0,29.718 h1.52
Drill Drawing:
  text ".Layer_Name" at 9.398,29.718 h1.52

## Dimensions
3.45,28.2 to 19.55,28.2 on Mechanical 3
23,0 to 23,25 on Mechanical 3
0,0 to 23,0 on Mechanical 3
